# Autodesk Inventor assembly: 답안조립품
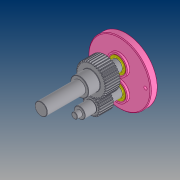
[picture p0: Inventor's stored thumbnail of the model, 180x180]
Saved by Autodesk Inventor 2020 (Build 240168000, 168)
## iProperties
Created: 2020-07
Part Number: 답안조립품
Document SubType Name: Assembly
Designer: PC312-
Author: PC312-
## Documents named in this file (6)
- C:\Users\PC312-\Desktop\700718V1009\답안조립품.iam
- C:\Users\PC312-\Desktop\700718V1009\본체.ipt
- C:\Users\PC312-\Desktop\700718V1009\커버.ipt
- C:\Users\PC312-\Desktop\700718V1009\베어링 608.ipt
- C:\Users\PC312-\Desktop\700718V1009\메인 축.ipt
- C:\Users\PC312-\Desktop\700718V1009\서브 축.ipt
